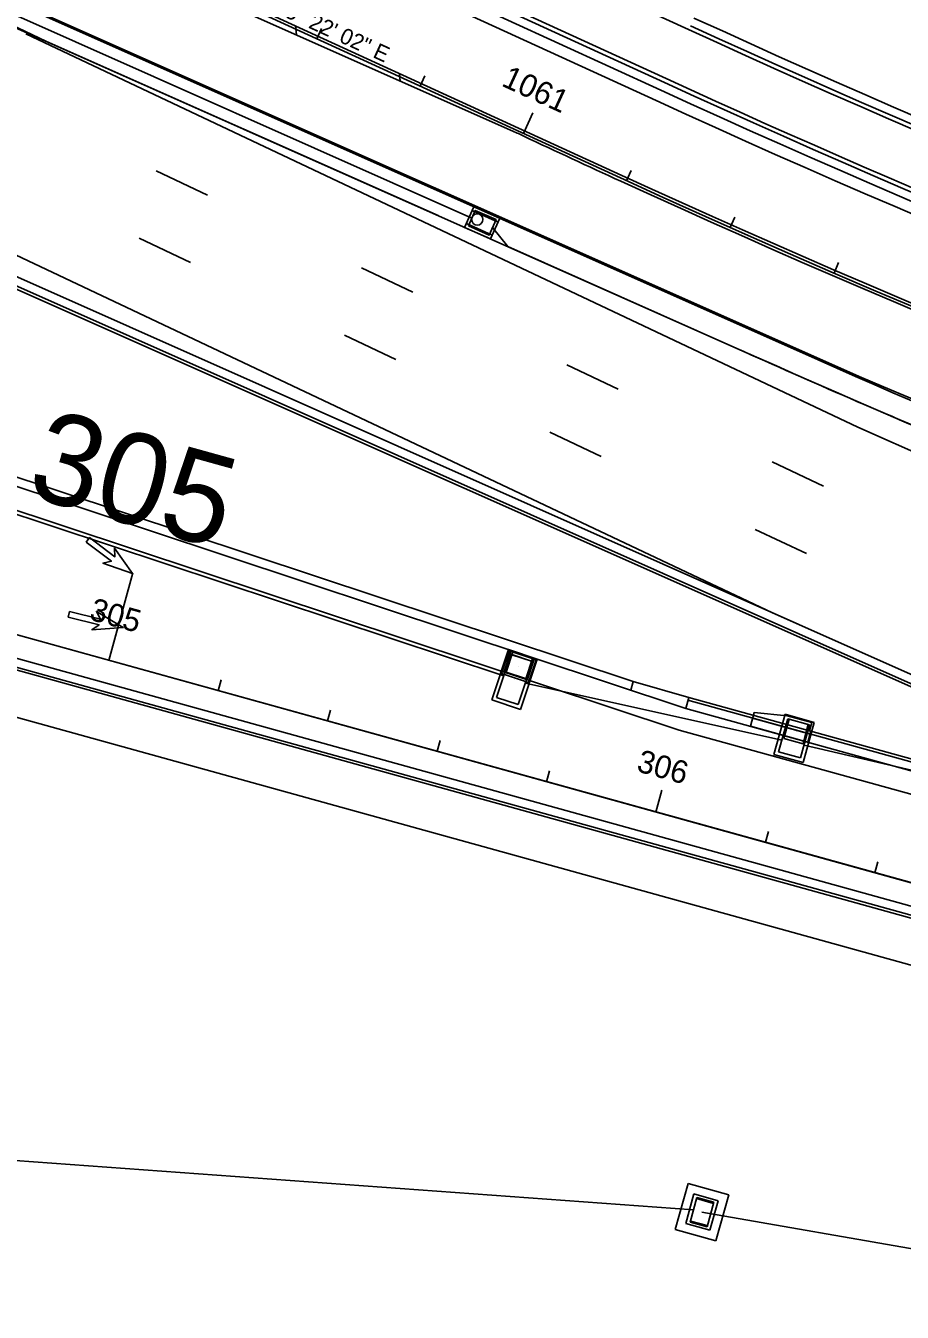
# Model space of a CAD drawing. Extents: x 468143 to 491361, y 1438528 to 1468730.
# Drawn here: x 488244.2 to 488398.6, y 1466655.8 to 1466882.5 of the extents above; entities that cross this region are included whole.
import ezdxf

# ---------------------------------------------------------------- set-up
doc = ezdxf.new("R2010")
doc.units = 0
doc.layers.add('Default', color=7, linetype='Continuous')
doc.layers.add('Xreference_dp', color=7, linetype='Continuous')

# ---------------------------------------------------------------- blocks, each defined once
blk = doc.blocks.new('POINT_DISPLAY')
at = {"layer": 'Default'}
blk.add_line((0, 0), (0, 0), dxfattribs=at)
blk = doc.blocks.new('InltCurb7_40')
at = {"layer": 'Default'}
for p, q in [((2.5, 4), (-2.5, 4)), ((-2.5, 4), (-2.5, 0)), ((2.5, 3.25), (-2.5, 3.25)), ((2.5, 0), (2.5, 4)), ((-2.5, 0.75), (2.5, 0.75)), ((-2.5, 0), (2.5, 0))]:
    blk.add_line(p, q, dxfattribs=at)
blk.add_lwpolyline([(-2, 0.5), (2, 0.5), (2, 3.5), (-2, 3.5)], close=True, dxfattribs=at)
blk.add_circle((-1.04, 2.19), 1, dxfattribs=at)
for p in [(-2, 3.5), (0, 4), (0, 3.5), (0, 3.5), (2, 3.5), (-2, 2), (-2, 2), (-2, 0.5), (0, 2), (0, 2), (0, 0.5), (0, 0.5), (0, 0), (0, 0), (2, 2), (2, 2), (2, 0.5)]:
    blk.add_blockref('POINT_DISPLAY', p, dxfattribs=at)
blk = doc.blocks.new('JBottom40x60')
at = {"layer": 'Default'}
for p, q in [((2.67, 3.67), (-2.67, 3.67)), ((-2.67, 3.67), (-2.67, -3.67)), ((-2, -3), (-2, 3)), ((-2, 3), (2, 3)), ((2, 3), (2, -3)), ((2.67, -3.67), (2.67, 3.67)), ((-2.67, -3.67), (2.67, -3.67)), ((2, -3), (-2, -3))]:
    blk.add_line(p, q, dxfattribs=at)
for p in [(-2, 3), (0, 3), (0, 3), (0, 3), (2, 3), (-2, 0), (-2, 0), (0, 0), (0, 0), (0, 0), (2, 0), (2, 0), (-2, -3), (0, -3), (0, -3), (0, -3), (2, -3)]:
    blk.add_blockref('POINT_DISPLAY', p, dxfattribs=at)
blk = doc.blocks.new('JBottom40x80_5')
at = {"layer": 'Default'}
for p, q in [((2.67, 4.67), (-2.67, 4.67)), ((-2.67, 4.67), (-2.67, -4.67)), ((2.67, -4.67), (2.67, 4.67)), ((-2, -4), (-2, 4)), ((-2, 4), (2, 4)), ((2, 4), (2, -4)), ((2, -4), (-2, -4)), ((-2.67, -4.67), (2.67, -4.67))]:
    blk.add_line(p, q, dxfattribs=at)
for p in [(-2, 4), (0, 4), (0, 4), (0, 4), (2, 4), (0, 0), (0, 0), (0, 0), (-2, 0), (-2, 0), (2, 0), (2, 0), (-2, -4), (0, -4), (0, -4), (0, -4), (2, -4)]:
    blk.add_blockref('POINT_DISPLAY', p, dxfattribs=at)
blk = doc.blocks.new('DAMerge_2')
at = {"layer": 'Default'}
blk.add_lwpolyline([(0.71, -4.09), (0, -3.39), (3.95, 0.56), (2.42, 0.68), (7.31, 3.21), (4.77, -1.68), (4.66, -0.15), (0.71, -4.09)], dxfattribs=at)
blk = doc.blocks.new('DAMerge_6')
at = {"layer": 'Default'}
blk.add_lwpolyline([(0.71, -4.09), (0, -3.39), (3.95, 0.56), (2.42, 0.68), (7.31, 3.21), (4.77, -1.68), (4.66, -0.15), (0.71, -4.09)], dxfattribs=at)

msp = doc.modelspace()

# ---------------------------------------------------------------- linework, layer by layer
at = {"layer": 'Xreference_dp'}
for p, q in [((487416.58, 1467283.18), (488348.99, 1466855.64)), ((488360.97, 1466881.77), (487949.57, 1467070.41)), ((488356.08, 1466871.09), (487944.63, 1467059.75)), ((488356.7, 1466872.45), (487945.26, 1467061.11)), ((488357.02, 1466873.14), (487945.57, 1467061.79)), ((488355.24, 1466869.27), (487943.78, 1467057.94)), ((488349.2, 1466856.09), (487937.68, 1467044.79)), ((487935.21, 1467039.47), (488330.03, 1466863.88)), ((487928.9, 1467025.88), (488383.77, 1466823.62)), ((487929.01, 1467026.11), (488391.4, 1466820.5)), ((487927.22, 1467022.25), (488369.43, 1466825.62)), ((487910.37, 1466985.96), (488420.21, 1466759.26)), ((487909.53, 1466984.15), (488419.4, 1466757.43)), ((487909.74, 1466984.6), (488419.6, 1466757.89)), ((488322.78, 1466848.55), (488180.27, 1466911.92)), ((488247.88, 1466879.67), (488180.27, 1466911.92)), ((488244.22, 1466881.02), (488390.75, 1466811.76)), ((488291.72, 1466882.45), (488291.89, 1466880.84)), ((488295.5, 1466880.16), (488296.33, 1466881.98)), ((488247.88, 1466879.67), (488316.83, 1466849)), ((488310.02, 1466874.06), (488310.16, 1466872.71)), ((488313.68, 1466871.83), (488314.51, 1466873.65)), ((488331.86, 1466863.49), (488333.53, 1466867.13)), ((487949.91, 1466856.31), (488673.07, 1466655.85)), ((488431.38, 1466722.84), (487949.91, 1466856.31)), ((488267.17, 1466856.9), (488276.21, 1466852.62)), ((488350.04, 1466855.16), (488350.87, 1466856.98)), ((487948.84, 1466852.46), (488430.58, 1466718.91)), ((488219.07, 1466853.09), (488375.75, 1466779.03)), ((487948.31, 1466850.53), (488430.05, 1466716.99)), ((487948.44, 1466851.01), (488430.18, 1466717.47)), ((488329.1, 1466843.55), (488326.44, 1466846.92)), ((488368.27, 1466846.93), (488369.08, 1466848.75)), ((488264.21, 1466845.02), (488273.25, 1466840.75)), ((487946.17, 1466842.82), (488427.91, 1466709.28)), ((488329.1, 1466843.55), (488369.43, 1466825.62)), ((488386.58, 1466838.89), (488387.38, 1466840.72)), ((488303.34, 1466839.8), (488312.38, 1466835.53)), ((488300.37, 1466827.93), (488309.41, 1466823.66)), ((488339.5, 1466822.71), (488348.54, 1466818.44)), ((488189.64, 1466820.51), (488351.19, 1466766.92)), ((488189.23, 1466819.03), (488360.45, 1466762.22)), ((488188.06, 1466815.2), (488359.29, 1466758.39)), ((488336.54, 1466810.84), (488345.58, 1466806.56)), ((488390.75, 1466811.76), (488434.84, 1466792.16)), ((488375.66, 1466805.62), (488384.7, 1466801.34)), ((488227.67, 1466801.35), (488328.41, 1466767.93)), ((488372.7, 1466793.74), (488381.75, 1466789.49)), ((488258.84, 1466770.67), (488263.11, 1466786.09)), ((488375.75, 1466779.03), (488439.82, 1466750.54)), ((488258.84, 1466770.67), (488260.98, 1466778.38)), ((488258.84, 1466770.67), (488259.91, 1466774.53)), ((488329.36, 1466772.36), (488328.02, 1466768.33)), ((488329.67, 1466772.26), (488328.49, 1466768.7)), ((488329.99, 1466772.15), (488328.81, 1466768.59)), ((488334.1, 1466770.79), (488329.36, 1466772.36)), ((488333.31, 1466770.52), (488329.83, 1466771.68)), ((488332.29, 1466767.44), (488333.47, 1466771)), ((488332.6, 1466767.33), (488333.78, 1466770.89)), ((488332.76, 1466766.75), (488334.1, 1466770.79)), ((488328.02, 1466768.33), (488332.76, 1466766.75)), ((488328.49, 1466768.7), (488332.6, 1466767.33)), ((488278.11, 1466765.33), (488278.65, 1466767.26)), ((488332.21, 1466766.67), (488377.39, 1466756.62)), ((488332.21, 1466766.67), (488377.39, 1466756.62)), ((488351.19, 1466766.92), (488350.78, 1466765.43)), ((488351.19, 1466766.92), (488360.99, 1466764.15)), ((488360.99, 1466764.15), (488360.45, 1466762.22)), ((488360.85, 1466763.67), (488437.13, 1466742.52)), ((488360.99, 1466764.15), (488437.26, 1466743)), ((488297.39, 1466759.99), (488297.92, 1466761.92)), ((488360.45, 1466762.22), (488436.73, 1466741.08)), ((488372.51, 1466761.47), (488371.84, 1466759.06)), ((488378.32, 1466760.9), (488372.51, 1466761.47)), ((488382.66, 1466759.7), (488378.32, 1466760.9)), ((488359.29, 1466758.39), (488435.39, 1466737.3)), ((488371.84, 1466759.06), (488381.96, 1466756.26)), ((488372.24, 1466760.51), (488382.36, 1466757.7)), ((488377.67, 1466757.45), (488378.07, 1466758.9)), ((488382.26, 1466758.25), (488382.66, 1466759.7)), ((488316.66, 1466754.65), (488317.19, 1466756.57)), ((488381.43, 1466756.41), (488381.83, 1466757.85)), ((488381.96, 1466756.26), (488382.5, 1466758.19)), ((488382.5, 1466758.19), (488382.26, 1466758.25)), ((488381.3, 1466755.75), (488428.07, 1466744.77)), ((488381.3, 1466755.75), (488428.07, 1466744.77)), ((488381.3, 1466755.75), (488428.07, 1466744.77)), ((488381.3, 1466755.75), (488428.07, 1466744.77)), ((488335.93, 1466749.3), (488336.47, 1466751.23)), ((488355.2, 1466743.96), (488356.27, 1466747.81)), ((488374.48, 1466738.62), (488375.01, 1466740.54)), ((488393.75, 1466733.27), (488394.29, 1466735.2)), ((488361.83, 1466673.89), (487963.15, 1466702.79)), ((488360.87, 1466678.52), (488358.62, 1466670.41)), ((488368.02, 1466676.54), (488360.87, 1466678.52)), ((488361.91, 1466676.68), (488360.47, 1466671.46)), ((488362.43, 1466676.04), (488361.24, 1466671.74)), ((488366.17, 1466675.5), (488361.91, 1466676.68)), ((488365.35, 1466675.03), (488362.38, 1466675.86)), ((488365.4, 1466675.21), (488362.43, 1466676.04)), ((488364.21, 1466670.92), (488365.4, 1466675.21)), ((488364.72, 1466670.28), (488366.17, 1466675.5)), ((488365.77, 1466668.43), (488368.02, 1466676.54)), ((488363.32, 1466673.48), (488415.46, 1466664.37)), ((488358.62, 1466670.41), (488365.77, 1466668.43)), ((488360.47, 1466671.46), (488364.72, 1466670.28)), ((488361.24, 1466671.74), (488364.21, 1466670.92)), ((488361.29, 1466671.92), (488364.26, 1466671.1))]:
    msp.add_line(p, q, dxfattribs=at)
msp.add_lwpolyline([(488377.73, 1466756.91), (488381.11, 1466755.98), (488382.04, 1466759.35), (488378.67, 1466760.29)], close=True, dxfattribs=at)
for centre, radius, start, end in [((489145.02, 1468591.69), 1909.86, 245.36712, 306.9274), ((489143.9, 1468591.41), 1816.82, 245.36787, 299.96455), ((489145.02, 1468591.69), 1837.36, 245.36712, 266.14562), ((489145.02, 1468591.69), 1836.86, 245.36712, 266.14562), ((489145.02, 1468591.69), 1838.86, 245.36712, 266.14562), ((489145.02, 1468591.69), 1842.86, 245.36712, 265.63392), ((489145.02, 1468591.69), 1878.86, 245.36712, 266.78234), ((489145.02, 1468591.69), 1878.86, 245.36712, 266.78234), ((489145.02, 1468591.69), 1881.11, 245.36712, 266.78234), ((489145.02, 1468591.69), 1880.36, 245.36712, 266.78234), ((489145.02, 1468591.69), 1891.36, 245.36712, 267.59092), ((489145.02, 1468591.69), 1890.61, 245.36712, 263.85174), ((489145.02, 1468591.69), 1892.86, 245.36712, 267.59092), ((489145.02, 1468591.69), 1894.86, 245.36712, 267.58634), ((488289.39, 1466772.51), 100, 64.8106, 66.0229), ((489145.02, 1468591.69), 1910.36, 244.81058, 245.37448), ((489145.02, 1468591.69), 1909.36, 245.36712, 267.72102), ((489145.02, 1468591.69), 1910.36, 245.37448, 267.72104), ((489412.39, 1469171.15), 2566.96, 246.02731, 251.49066), ((489201.99, 1468687.26), 2039.33, 245.90518, 247.12838), ((489095.84, 1468425.01), 1752.58, 246.02731, 253.56076), ((489145.02, 1468591.69), 1924.86, 246.95075, 267.69896)]:
    msp.add_arc(centre, radius, start, end, dxfattribs=at)

# ---------------------------------------------------------------- block references
for name, p, rotation in [('InltCurb7_40', (488323.8, 1466845.91), -23.97270369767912), ('DAMerge_6', (488258.84, 1466792.76), -82.29263665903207), ('DAMerge_2', (488254.84, 1466781.01), -58.68441390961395), ('DAMerge_6', (488254.84, 1466781.01), -58.68441390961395), ('JBottom40x80_5', (488330.31, 1466767.3), -18.3534452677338), ('POINT_DISPLAY', (488329.32, 1466770.14), -18.3534452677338), ('POINT_DISPLAY', (488329.32, 1466770.14), -18.3534452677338), ('POINT_DISPLAY', (488329.83, 1466771.68), -18.3534452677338), ('POINT_DISPLAY', (488331.57, 1466771.1), -18.3534452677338), ('POINT_DISPLAY', (488331.57, 1466771.1), -18.3534452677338), ('POINT_DISPLAY', (488331.73, 1466771.57), -18.3534452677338), ('POINT_DISPLAY', (488331.73, 1466771.57), -18.3534452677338), ('POINT_DISPLAY', (488333.31, 1466770.52), -18.3534452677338), ('POINT_DISPLAY', (488328.81, 1466768.59), -18.3534452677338), ('POINT_DISPLAY', (488330.39, 1466767.54), -18.3534452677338), ('POINT_DISPLAY', (488330.55, 1466768.02), -18.3534452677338), ('POINT_DISPLAY', (488330.55, 1466768.02), -18.3534452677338), ('POINT_DISPLAY', (488331.06, 1466769.56), -18.3534452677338), ('POINT_DISPLAY', (488331.06, 1466769.56), -18.3534452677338), ('POINT_DISPLAY', (488332.29, 1466767.44), -18.3534452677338), ('POINT_DISPLAY', (488332.8, 1466768.98), -18.3534452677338), ('POINT_DISPLAY', (488332.8, 1466768.98), -18.3534452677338), ('JBottom40x60', (488379.55, 1466756.93), -15.49388888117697), ('POINT_DISPLAY', (488378.2, 1466758.6), -15.49388888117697), ('POINT_DISPLAY', (488378.2, 1466758.6), -15.49388888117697), ('POINT_DISPLAY', (488378.67, 1466760.29), -15.49388888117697), ('POINT_DISPLAY', (488380.35, 1466759.82), -15.49388888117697), ('POINT_DISPLAY', (488380.35, 1466759.82), -15.49388888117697), ('POINT_DISPLAY', (488380.49, 1466760.3), -15.49388888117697), ('POINT_DISPLAY', (488382.04, 1466759.35), -15.49388888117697), ('POINT_DISPLAY', (488377.73, 1466756.91), -15.49388888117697), ('POINT_DISPLAY', (488379.42, 1466756.45), -15.49388888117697), ('POINT_DISPLAY', (488379.42, 1466756.45), -15.49388888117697), ('POINT_DISPLAY', (488379.55, 1466756.93), -15.49388888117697), ('POINT_DISPLAY', (488379.55, 1466756.93), -15.49388888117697), ('POINT_DISPLAY', (488379.89, 1466758.13), -15.49388888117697), ('POINT_DISPLAY', (488379.89, 1466758.13), -15.49388888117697), ('POINT_DISPLAY', (488381.57, 1466757.66), -15.49388888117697), ('POINT_DISPLAY', (488381.57, 1466757.66), -15.49388888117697), ('POINT_DISPLAY', (488381.11, 1466755.98), -15.49388888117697), ('POINT_DISPLAY', (488362.38, 1466675.86), -15.493889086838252), ('POINT_DISPLAY', (488363.86, 1466675.44), -15.493889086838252), ('POINT_DISPLAY', (488363.86, 1466675.44), -15.493889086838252), ('POINT_DISPLAY', (488364.04, 1466676.09), -15.493889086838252), ('POINT_DISPLAY', (488365.35, 1466675.03), -15.493889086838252), ('POINT_DISPLAY', (488361.83, 1466673.89), -15.493889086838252), ('POINT_DISPLAY', (488361.83, 1466673.89), -15.493889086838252), ('POINT_DISPLAY', (488363.32, 1466673.48), -15.493889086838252), ('POINT_DISPLAY', (488363.32, 1466673.48), -15.493889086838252), ('POINT_DISPLAY', (488364.8, 1466673.06), -15.493889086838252), ('POINT_DISPLAY', (488364.8, 1466673.06), -15.493889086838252), ('POINT_DISPLAY', (488361.29, 1466671.92), -15.493889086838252), ('POINT_DISPLAY', (488362.6, 1466670.87), -15.493889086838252), ('POINT_DISPLAY', (488362.77, 1466671.51), -15.493889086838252), ('POINT_DISPLAY', (488362.77, 1466671.51), -15.493889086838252), ('POINT_DISPLAY', (488364.26, 1466671.1), -15.493889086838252)]:
    msp.add_blockref(name, p, dxfattribs=dict(at, rotation=rotation))
msp.add_blockref('POINT_DISPLAY', (488369.43, 1466825.62), dxfattribs=at)

# ---------------------------------------------------------------- texts
for s, height, rotation, p in [('S 65%%d 22\' 02" E', 2.8, 335.3671, (488284.55, 1466886.42)), ('1061', 4, 335.3671, (488327.83, 1466871.94)), ('305', 16, 344.5061, (488244.01, 1466799.75)), ('305', 4, 344.5061, (488255.25, 1466777.89)), ('306', 4, 344.5061, (488351.62, 1466751.18))]:
    msp.add_text(s, height=height, rotation=rotation, dxfattribs=at).set_placement(p)

doc.saveas('drawing.dxf')
